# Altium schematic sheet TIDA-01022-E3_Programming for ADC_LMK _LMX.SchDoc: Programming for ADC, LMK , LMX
size 431 x 279 mm; Date: Not shown in title block; ApprovedBy: Not shown in title block; CheckedBy: Not shown in title block; Author: Not shown in title block; CompanyName: Not shown in title block; DrawnBy: Avinash N; Engineer: Anbu Mani; Organization: Not shown in title block; Address1: Not shown in title block; Address2: Not shown in title block; Address3: Not shown in title block; Address4: Not shown in title block; DocumentNumber: 1; Revision: Use project parameter SCH_Rev; SheetNumber: 15; SheetTotal: 26; PageSetup: Record=PageOptions¦CenterHorizontal=True¦CenterVertical=True¦PrintScale=1.00¦XCorrection=1.00¦YCorrection=1.00¦PrintKind=0¦BorderSize=5000000¦LeftOffset=0¦BottomOffset=0¦Orientation=2¦PaperLength=1000¦PaperWidth=1000¦Scale=100¦PaperSource=15¦PrintQuality=600¦MediaType=1¦DitherType=10¦PaperKind=Letter¦PrintScaleMode=1
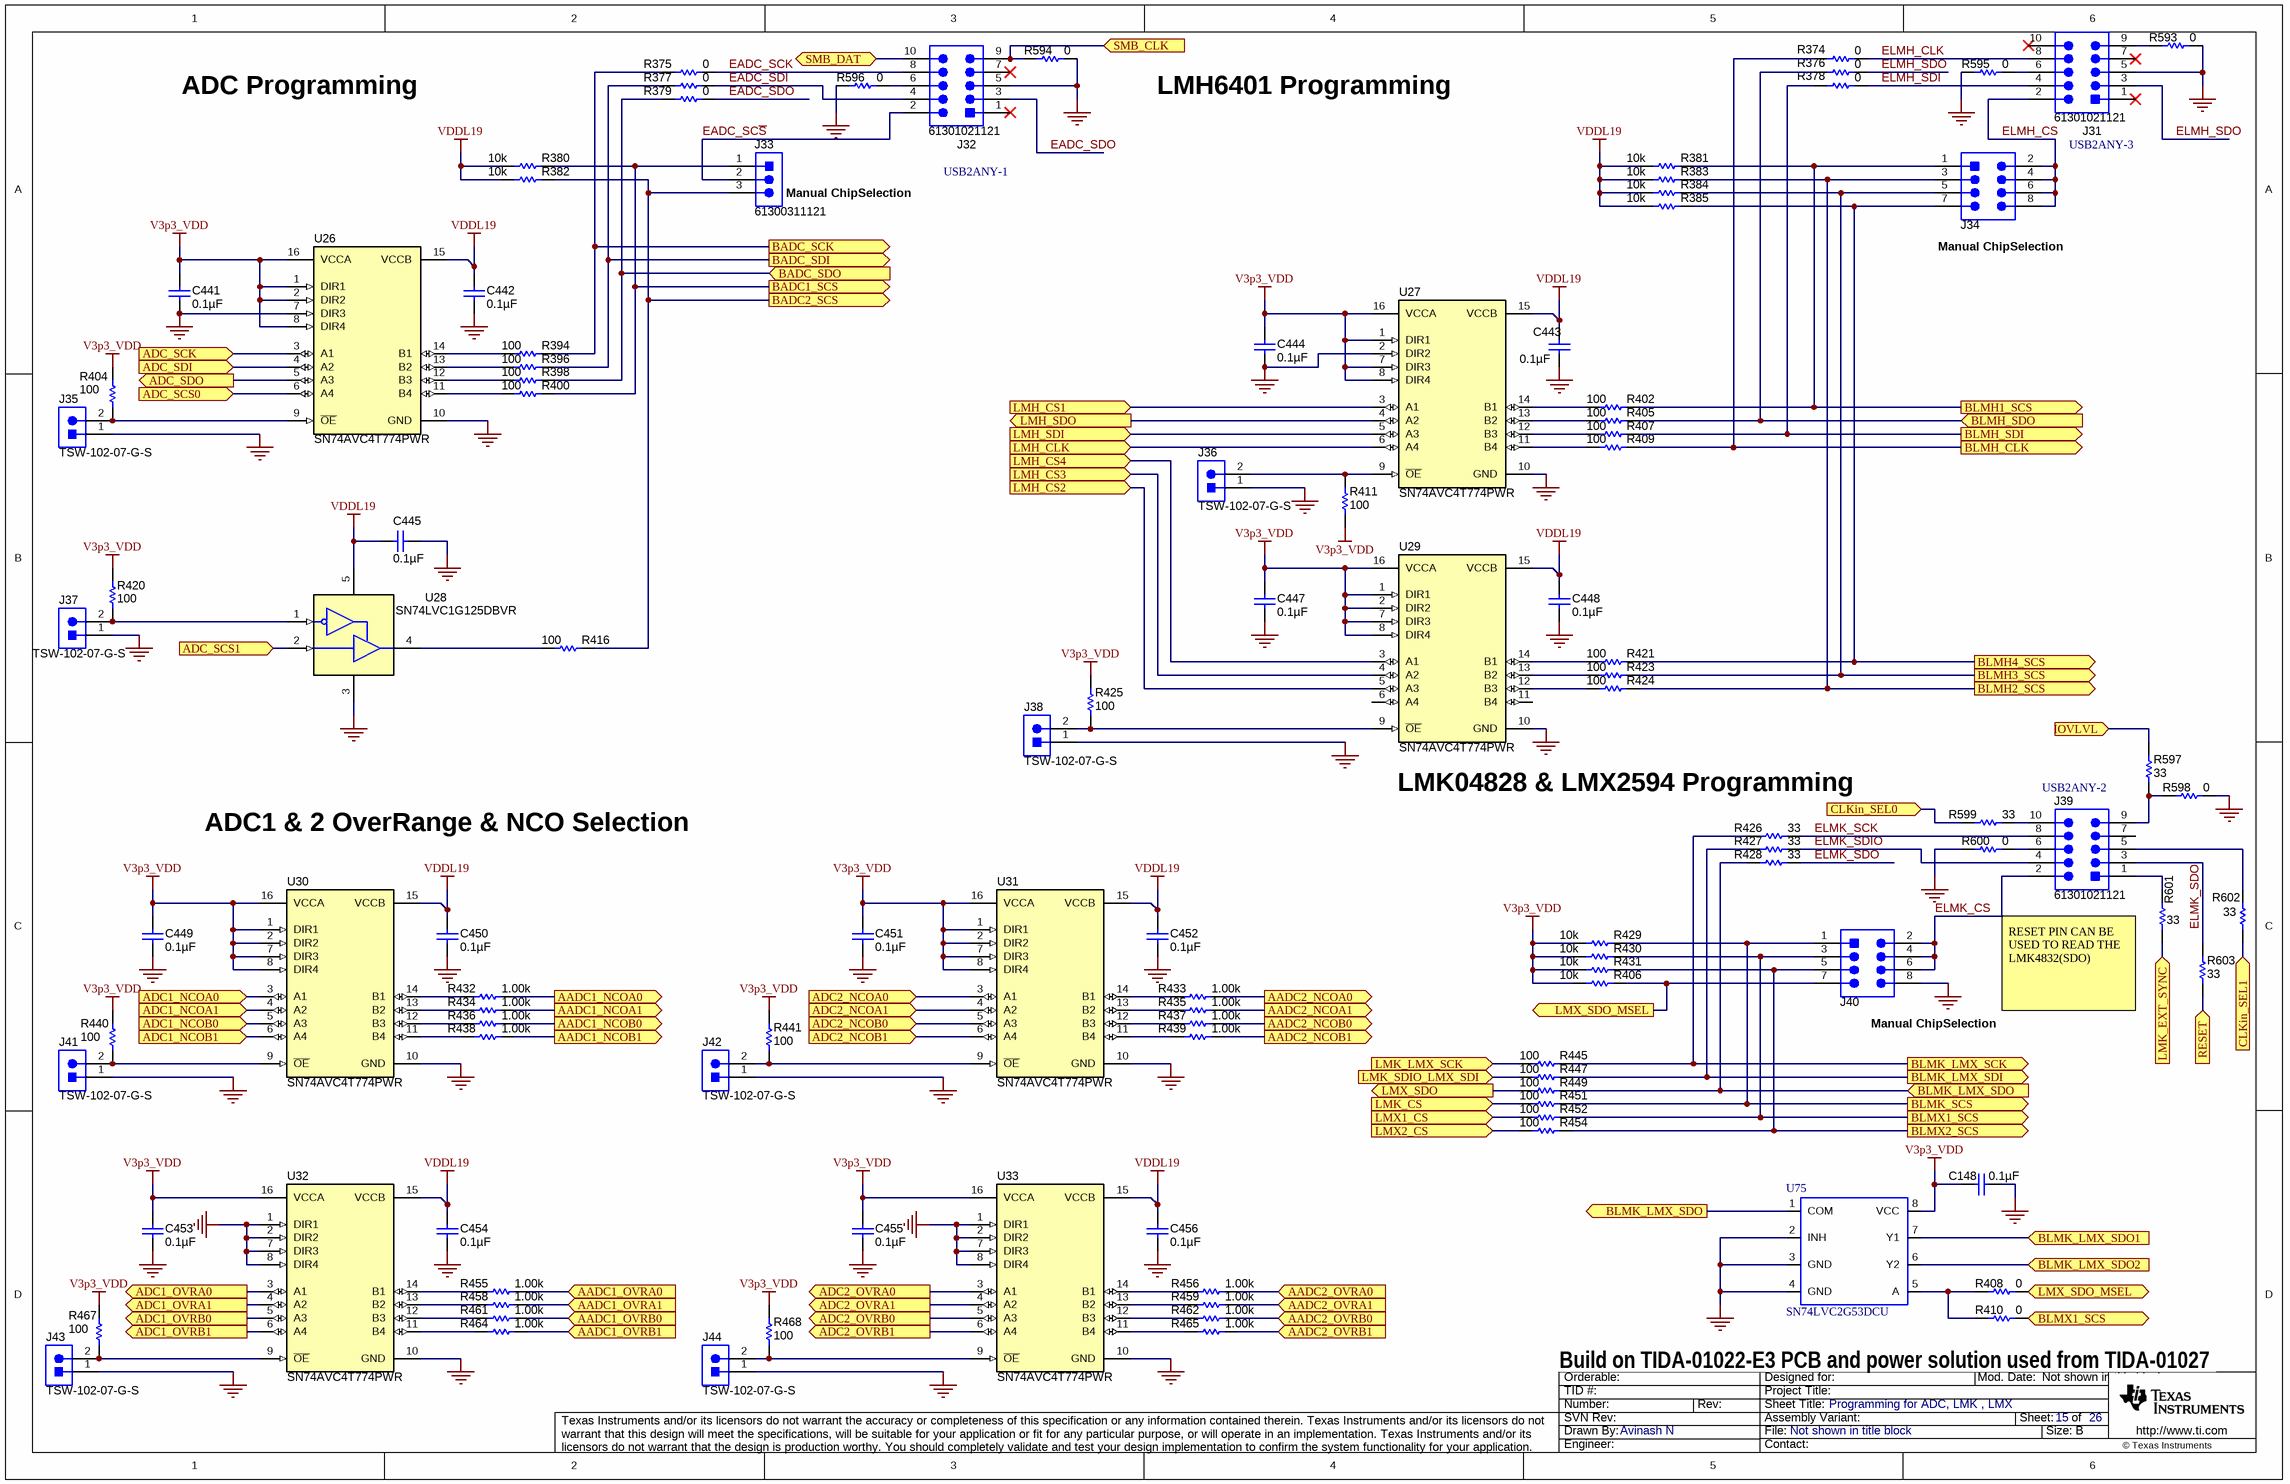
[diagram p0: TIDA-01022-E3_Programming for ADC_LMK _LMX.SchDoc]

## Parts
C148  ValueDisplayed: 0.1µF  [0603]  (hidden comment: C0603C104J3RACTU)
C441  ValueDisplayed: 0.1µF  [0603]  (hidden comment: C0603C104J3RACTU)
C442  ValueDisplayed: 0.1µF  [0603]  (hidden comment: C0603C104J3RACTU)
C443  ValueDisplayed: 0.1µF  [0603]  (hidden comment: C0603C104J3RACTU)
C444  ValueDisplayed: 0.1µF  [0603]  (hidden comment: C0603C104J3RACTU)
C445  ValueDisplayed: 0.1µF  [0603]  (hidden comment: C0603C104J3RACTU)
C447  ValueDisplayed: 0.1µF  [0603]  (hidden comment: C0603C104J3RACTU)
C448  ValueDisplayed: 0.1µF  [0603]  (hidden comment: C0603C104J3RACTU)
C449  ValueDisplayed: 0.1µF  [0603]  (hidden comment: C0603C104J3RACTU)
C450  ValueDisplayed: 0.1µF  [0603]  (hidden comment: C0603C104J3RACTU)
C451  ValueDisplayed: 0.1µF  [0603]  (hidden comment: C0603C104J3RACTU)
C452  ValueDisplayed: 0.1µF  [0603]  (hidden comment: C0603C104J3RACTU)
C453  ValueDisplayed: 0.1µF  [0603]  (hidden comment: C0603C104J3RACTU)
C454  ValueDisplayed: 0.1µF  [0603]  (hidden comment: C0603C104J3RACTU)
C455  ValueDisplayed: 0.1µF  [0603]  (hidden comment: C0603C104J3RACTU)
C456  ValueDisplayed: 0.1µF  [0603]  (hidden comment: C0603C104J3RACTU)
J31  61301021121  [WURTH_61301021121]
J32  61301021121  [WURTH_61301021121]
J33  61300311121  [WURTH_61300311121]
J34  TSW-104-07-G-D  [TSW-104-07-G-D]  (value not drawn)
J35  TSW-102-07-G-S  [TSW-102-07-G-S]
J36  TSW-102-07-G-S  [TSW-102-07-G-S]
J37  TSW-102-07-G-S  [TSW-102-07-G-S]
J38  TSW-102-07-G-S  [TSW-102-07-G-S]
J39  61301021121  [WURTH_61301021121]
J40  TSW-104-07-G-D  [TSW-104-07-G-D]  (value not drawn)
J41  TSW-102-07-G-S  [TSW-102-07-G-S]
J42  TSW-102-07-G-S  [TSW-102-07-G-S]
J43  TSW-102-07-G-S  [TSW-102-07-G-S]
J44  TSW-102-07-G-S  [TSW-102-07-G-S]
R374  ValueDisplayed: 0  [0603]  (hidden comment: CRCW06030000Z0EA)
R375  ValueDisplayed: 0  [0603]  (hidden comment: CRCW06030000Z0EA)
R376  ValueDisplayed: 0  [0603]  (hidden comment: CRCW06030000Z0EA)
R377  ValueDisplayed: 0  [0603]  (hidden comment: CRCW06030000Z0EA)
R378  ValueDisplayed: 0  [0603]  (hidden comment: CRCW06030000Z0EA)
R379  ValueDisplayed: 0  [0603]  (hidden comment: CRCW06030000Z0EA)
R380  ValueDisplayed: 10k  [0603]  (hidden comment: CRCW060310K0JNEA)
R381  ValueDisplayed: 10k  [0603]  (hidden comment: CRCW060310K0JNEA)
R382  ValueDisplayed: 10k  [0603]  (hidden comment: CRCW060310K0JNEA)
R383  ValueDisplayed: 10k  [0603]  (hidden comment: CRCW060310K0JNEA)
R384  ValueDisplayed: 10k  [0603]  (hidden comment: CRCW060310K0JNEA)
R385  ValueDisplayed: 10k  [0603]  (hidden comment: CRCW060310K0JNEA)
R394  ValueDisplayed: 100  [0603]  (hidden comment: RC0603FR-07100RL)
R396  ValueDisplayed: 100  [0603]  (hidden comment: RC0603FR-07100RL)
R398  ValueDisplayed: 100  [0603]  (hidden comment: RC0603FR-07100RL)
R400  ValueDisplayed: 100  [0603]  (hidden comment: RC0603FR-07100RL)
R402  ValueDisplayed: 100  [0603]  (hidden comment: RC0603FR-07100RL)
R404  ValueDisplayed: 100  [0603]  (hidden comment: RC0603FR-07100RL)
R405  ValueDisplayed: 100  [0603]  (hidden comment: RC0603FR-07100RL)
R406  ValueDisplayed: 10k  [0603]  (hidden comment: CRCW060310K0JNEA)
R407  ValueDisplayed: 100  [0603]  (hidden comment: RC0603FR-07100RL)
R408  ValueDisplayed: 0  [0603]  (hidden comment: CRCW06030000Z0EA)
R409  ValueDisplayed: 100  [0603]  (hidden comment: RC0603FR-07100RL)
R410  ValueDisplayed: 0  [0603]  (hidden comment: CRCW06030000Z0EA)
R411  ValueDisplayed: 100  [0603]  (hidden comment: RC0603FR-07100RL)
R416  ValueDisplayed: 100  [0603]  (hidden comment: RC0603FR-07100RL)
R420  ValueDisplayed: 100  [0603]  (hidden comment: RC0603FR-07100RL)
R421  ValueDisplayed: 100  [0603]  (hidden comment: RC0603FR-07100RL)
R423  ValueDisplayed: 100  [0603]  (hidden comment: RC0603FR-07100RL)
R424  ValueDisplayed: 100  [0603]  (hidden comment: RC0603FR-07100RL)
R425  ValueDisplayed: 100  [0603]  (hidden comment: RC0603FR-07100RL)
R426  ValueDisplayed: 33  [0603]  (hidden comment: CRCW060333R0JNEA)
R427  ValueDisplayed: 33  [0603]  (hidden comment: CRCW060333R0JNEA)
R428  ValueDisplayed: 33  [0603]  (hidden comment: CRCW060333R0JNEA)
R429  ValueDisplayed: 10k  [0603]  (hidden comment: CRCW060310K0JNEA)
R430  ValueDisplayed: 10k  [0603]  (hidden comment: CRCW060310K0JNEA)
R431  ValueDisplayed: 10k  [0603]  (hidden comment: CRCW060310K0JNEA)
R432  ValueDisplayed: 1.00k  [0603]  (hidden comment: CRCW06031K00FKEA)
R433  ValueDisplayed: 1.00k  [0603]  (hidden comment: CRCW06031K00FKEA)
R434  ValueDisplayed: 1.00k  [0603]  (hidden comment: CRCW06031K00FKEA)
R435  ValueDisplayed: 1.00k  [0603]  (hidden comment: CRCW06031K00FKEA)
R436  ValueDisplayed: 1.00k  [0603]  (hidden comment: CRCW06031K00FKEA)
R437  ValueDisplayed: 1.00k  [0603]  (hidden comment: CRCW06031K00FKEA)
R438  ValueDisplayed: 1.00k  [0603]  (hidden comment: CRCW06031K00FKEA)
R439  ValueDisplayed: 1.00k  [0603]  (hidden comment: CRCW06031K00FKEA)
R440  ValueDisplayed: 100  [0603]  (hidden comment: RC0603FR-07100RL)
R441  ValueDisplayed: 100  [0603]  (hidden comment: RC0603FR-07100RL)
R445  ValueDisplayed: 100  [0603]  (hidden comment: RC0603FR-07100RL)
R447  ValueDisplayed: 100  [0603]  (hidden comment: RC0603FR-07100RL)
R449  ValueDisplayed: 100  [0603]  (hidden comment: RC0603FR-07100RL)
R451  ValueDisplayed: 100  [0603]  (hidden comment: RC0603FR-07100RL)
R452  ValueDisplayed: 100  [0603]  (hidden comment: RC0603FR-07100RL)
R454  ValueDisplayed: 100  [0603]  (hidden comment: RC0603FR-07100RL)
R455  ValueDisplayed: 1.00k  [0603]  (hidden comment: CRCW06031K00FKEA)
R456  ValueDisplayed: 1.00k  [0603]  (hidden comment: CRCW06031K00FKEA)
R458  ValueDisplayed: 1.00k  [0603]  (hidden comment: CRCW06031K00FKEA)
R459  ValueDisplayed: 1.00k  [0603]  (hidden comment: CRCW06031K00FKEA)
R461  ValueDisplayed: 1.00k  [0603]  (hidden comment: CRCW06031K00FKEA)
R462  ValueDisplayed: 1.00k  [0603]  (hidden comment: CRCW06031K00FKEA)
R464  ValueDisplayed: 1.00k  [0603]  (hidden comment: CRCW06031K00FKEA)
R465  ValueDisplayed: 1.00k  [0603]  (hidden comment: CRCW06031K00FKEA)
R467  ValueDisplayed: 100  [0603]  (hidden comment: RC0603FR-07100RL)
R468  ValueDisplayed: 100  [0603]  (hidden comment: RC0603FR-07100RL)
R593  ValueDisplayed: 0  [0603]  (hidden comment: CRCW06030000Z0EA)
R594  ValueDisplayed: 0  [0603]  (hidden comment: CRCW06030000Z0EA)
R595  ValueDisplayed: 0  [0603]  (hidden comment: CRCW06030000Z0EA)
R596  ValueDisplayed: 0  [0603]  (hidden comment: CRCW06030000Z0EA)
R597  ValueDisplayed: 33  [0603]  (hidden comment: CRCW060333R0JNEA)
R598  ValueDisplayed: 0  [0603]  (hidden comment: CRCW06030000Z0EA)
R599  ValueDisplayed: 33  [0603]  (hidden comment: CRCW060333R0JNEA)
R600  ValueDisplayed: 0  [0603]  (hidden comment: CRCW06030000Z0EA)
R601  ValueDisplayed: 33  [0603]  (hidden comment: CRCW060333R0JNEA)
R602  ValueDisplayed: 33  [0603]  (hidden comment: CRCW060333R0JNEA)
R603  ValueDisplayed: 33  [0603]  (hidden comment: CRCW060333R0JNEA)
U26  SN74AVC4T774PWR  [PW0016A_N]
U27  SN74AVC4T774PWR  [PW0016A_N]
U28  SN74LVC1G125DBVR  [DBV0005A_N]
U29  SN74AVC4T774PWR  [PW0016A_N]
U30  SN74AVC4T774PWR  [PW0016A_N]
U31  SN74AVC4T774PWR  [PW0016A_N]
U32  SN74AVC4T774PWR  [PW0016A_N]
U33  SN74AVC4T774PWR  [PW0016A_N]
U75  SN74LVC2G53DCU  [DCU0008A_N]

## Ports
AADC1_NCOA0 (out), AADC1_NCOA1 (out), AADC1_NCOB0 (out), AADC1_NCOB1 (out), AADC1_OVRA0 (in), AADC1_OVRA1 (in), AADC1_OVRB0 (in), AADC1_OVRB1 (in), AADC2_NCOA0 (out), AADC2_NCOA1 (out), AADC2_NCOB0 (out), AADC2_NCOB1 (out), AADC2_OVRA0 (in), AADC2_OVRA1 (in), AADC2_OVRB0 (in), AADC2_OVRB1 (in), ADC1_NCOA0 (in), ADC1_NCOA1 (in), ADC1_NCOB0 (in), ADC1_NCOB1 (in), ADC1_OVRA0 (out), ADC1_OVRA1 (out), ADC1_OVRB0 (out), ADC1_OVRB1 (out), ADC2_NCOA0 (in), ADC2_NCOA1 (in), ADC2_NCOB0 (in), ADC2_NCOB1 (in), ADC2_OVRA0 (out), ADC2_OVRA1 (out), ADC2_OVRB0 (out), ADC2_OVRB1 (out), ADC_SCK (in), ADC_SCS0 (in), ADC_SCS1 (in), ADC_SDI (in), ADC_SDO (out), BADC1_SCS (out), BADC2_SCS (out), BADC_SCK (out), BADC_SDI (out), BADC_SDO (in), BLMH1_SCS (out), BLMH2_SCS (out), BLMH3_SCS (out), BLMH4_SCS (out), BLMH_CLK (out), BLMH_SDI (out), BLMH_SDO (in), BLMK_LMX_SCK (out), BLMK_LMX_SDI (out), BLMK_LMX_SDO1 (in), BLMK_LMX_SDO2 (in), BLMK_LMX_SDO (in), BLMK_LMX_SDO (out), BLMK_SCS (out), BLMX1_SCS (in), BLMX1_SCS (out), BLMX2_SCS (out), CLKin_SEL0 (in), CLKin_SEL1 (in), IOVLVL (in), LMH_CLK (in), LMH_CS1 (in), LMH_CS2 (in), LMH_CS3 (in), LMH_CS4 (in), LMH_SDI (in), LMH_SDO (out), LMK_CS (in), LMK_EXT_SYNC (in), LMK_LMX_SCK (in), LMK_SDIO_LMX_SDI (in), LMX1_CS (in), LMX2_CS (in), LMX_SDO (out), LMX_SDO_MSEL (in), LMX_SDO_MSEL (out), RESET (in), SMB_CLK (in), SMB_DAT (bidir)

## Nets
GND_PLL: C148.2 C441.1 C442.1 C443.1 C444.1 C445.1 C447.1 C448.1 C449.1 C450.1 C451.1 C452.1 C453.1 C454.1 C455.1 C456.1 J31.5 J32.5 J35.1 J36.1 J37.1 J38.1 J40.8 J41.1 J42.1 J43.1 J44.1 R593.2 R594.2 R595.1 R596.1 R598.2 R600.1 U26.7(DIR3) U26.10(GND) U27.2(DIR2) U27.10(GND) U28.3(GND) U29.10(GND) U30.10(GND) U31.10(GND) U32.1(DIR1) U32.2(DIR2) U32.7(DIR3) U32.8(DIR4) U32.10(GND) U33.1(DIR1) U33.2(DIR2) U33.7(DIR3) U33.8(DIR4) U33.10(GND) U75.2(INH) U75.3(GND) U75.4(GND)
V3p3_VDD: C148.1 C441.2 C444.2 C447.2 C449.2 C451.2 C453.2 C455.2 R404.1 R406.1 R411.1 R420.1 R425.1 R429.1 R430.1 R431.1 R440.1 R441.1 R467.1 R468.1 U26.1(DIR1) U26.2(DIR2) U26.8(DIR4) U26.16(VCCA) U27.1(DIR1) U27.7(DIR3) U27.8(DIR4) U27.16(VCCA) U29.1(DIR1) U29.2(DIR2) U29.7(DIR3) U29.8(DIR4) U29.16(VCCA) U30.1(DIR1) U30.2(DIR2) U30.7(DIR3) U30.8(DIR4) U30.16(VCCA) U31.1(DIR1) U31.2(DIR2) U31.7(DIR3) U31.8(DIR4) U31.16(VCCA) U32.16(VCCA) U33.16(VCCA) U75.8(VCC)
VDDL19: C442.2 C443.2 C445.2 C448.2 C450.2 C452.2 C454.2 C456.2 R380.1 R381.1 R382.1 R383.1 R384.1 R385.1 U26.15(VCCB) U27.15(VCCB) U28.5(VCC) U29.15(VCCB) U30.15(VCCB) U31.15(VCCB) U32.15(VCCB) U33.15(VCCB)
AADC1_NCOA0: R432.2 ; port AADC1_NCOA0
AADC1_NCOA1: R434.2 ; port AADC1_NCOA1
AADC1_NCOB0: R436.2 ; port AADC1_NCOB0
AADC1_NCOB1: R438.2 ; port AADC1_NCOB1
AADC1_OVRA0: R455.2 ; port AADC1_OVRA0
AADC1_OVRA1: R458.2 ; port AADC1_OVRA1
AADC1_OVRB0: R461.2 ; port AADC1_OVRB0
AADC1_OVRB1: R464.2 ; port AADC1_OVRB1
AADC2_NCOA0: R433.2 ; port AADC2_NCOA0
AADC2_NCOA1: R435.2 ; port AADC2_NCOA1
AADC2_NCOB0: R437.2 ; port AADC2_NCOB0
AADC2_NCOB1: R439.2 ; port AADC2_NCOB1
AADC2_OVRA0: R456.2 ; port AADC2_OVRA0
AADC2_OVRA1: R459.2 ; port AADC2_OVRA1
AADC2_OVRB0: R462.2 ; port AADC2_OVRB0
AADC2_OVRB1: R465.2 ; port AADC2_OVRB1
ADC1_NCOA0: U30.3(A1) ; port ADC1_NCOA0
ADC1_NCOA1: U30.4(A2) ; port ADC1_NCOA1
ADC1_NCOB0: U30.5(A3) ; port ADC1_NCOB0
ADC1_NCOB1: U30.6(A4) ; port ADC1_NCOB1
ADC1_OVRA0: U32.3(A1) ; port ADC1_OVRA0
ADC1_OVRA1: U32.4(A2) ; port ADC1_OVRA1
ADC1_OVRB0: U32.5(A3) ; port ADC1_OVRB0
ADC1_OVRB1: U32.6(A4) ; port ADC1_OVRB1
ADC2_NCOA0: U31.3(A1) ; port ADC2_NCOA0
ADC2_NCOA1: U31.4(A2) ; port ADC2_NCOA1
ADC2_NCOB0: U31.5(A3) ; port ADC2_NCOB0
ADC2_NCOB1: U31.6(A4) ; port ADC2_NCOB1
ADC2_OVRA0: U33.3(A1) ; port ADC2_OVRA0
ADC2_OVRA1: U33.4(A2) ; port ADC2_OVRA1
ADC2_OVRB0: U33.5(A3) ; port ADC2_OVRB0
ADC2_OVRB1: U33.6(A4) ; port ADC2_OVRB1
ADC_SCK: U26.3(A1) ; port ADC_SCK
ADC_SCS0: U26.6(A4) ; port ADC_SCS0
ADC_SCS1: U28.2(A) ; port ADC_SCS1
ADC_SDI: U26.4(A2) ; port ADC_SDI
ADC_SDO: U26.5(A3) ; port ADC_SDO
BADC1_SCS: J33.1 R380.2 R400.2 ; port BADC1_SCS
BADC2_SCS: J33.3 R382.2 R416.2 ; port BADC2_SCS
BADC_SCK: R375.1 R394.2 ; port BADC_SCK
BADC_SDI: R377.1 R396.2 ; port BADC_SDI
BADC_SDO: R379.1 R398.2 ; port BADC_SDO
BLMH1_SCS: J34.1 R381.2 R402.2 ; port BLMH1_SCS
BLMH2_SCS: J34.3 R383.2 R424.2 ; port BLMH2_SCS
BLMH3_SCS: J34.5 R384.2 R423.2 ; port BLMH3_SCS
BLMH4_SCS: J34.7 R385.2 R421.2 ; port BLMH4_SCS
BLMH_CLK: R374.1 R409.2 ; port BLMH_CLK
BLMH_SDI: R378.1 R407.2 ; port BLMH_SDI
BLMH_SDO: R376.1 R405.2 ; port BLMH_SDO
BLMK_LMX_SCK: R426.1 R445.2 ; port BLMK_LMX_SCK
BLMK_LMX_SDI: R427.1 R447.2 ; port BLMK_LMX_SDI
BLMK_LMX_SDO: R428.1 R449.2 U75.1(COM) ; port BLMK_LMX_SDO
BLMK_LMX_SDO1: U75.7(Y1) ; port BLMK_LMX_SDO1
BLMK_LMX_SDO2: U75.6(Y2) ; port BLMK_LMX_SDO2
BLMK_SCS: J40.1 R429.2 R451.2 ; port BLMK_SCS
BLMX1_SCS: J40.3 R410.2 R430.2 R452.2 ; port BLMX1_SCS
BLMX2_SCS: J40.5 R431.2 R454.2 ; port BLMX2_SCS
CLKin_SEL0: R599.2 ; port CLKin_SEL0
CLKin_SEL1: R602.1 ; port CLKin_SEL1
EADC_SCK: J32.8 R375.2
EADC_SC~{S}: J32.2 J33.2
EADC_SDI: J32.4 R377.2
EADC_SDO: J32.3 R379.2
ELMH_CLK: J31.8 R374.2
ELMH_CS: J31.2 J34.2 J34.4 J34.6 J34.8
ELMH_SDI: J31.4 R378.2
ELMH_SDO: J31.3 R376.2
ELMK_CS: J39.2 J40.2 J40.4 J40.6
ELMK_SCK: J39.8 R426.2
ELMK_SDIO: J39.4 R427.2
ELMK_SDO: J39.3 R428.2 R603.2
IOVLVL: R597.2 ; port IOVLVL
LMH_CLK: U27.6(A4) ; port LMH_CLK
LMH_CS1: U27.3(A1) ; port LMH_CS1
LMH_CS2: U29.5(A3) ; port LMH_CS2
LMH_CS3: U29.4(A2) ; port LMH_CS3
LMH_CS4: U29.3(A1) ; port LMH_CS4
LMH_SDI: U27.5(A3) ; port LMH_SDI
LMH_SDO: U27.4(A2) ; port LMH_SDO
LMK_CS: R451.1 ; port LMK_CS
LMK_EXT_SYNC: R601.1 ; port LMK_EXT_SYNC
LMK_LMX_SCK: R445.1 ; port LMK_LMX_SCK
LMK_SDIO_LMX_SDI: R447.1 ; port LMK_SDIO_LMX_SDI
LMX1_CS: R452.1 ; port LMX1_CS
LMX2_CS: R454.1 ; port LMX2_CS
LMX_SDO: R449.1 ; port LMX_SDO
LMX_SDO_MSEL: J40.7 R406.2 R408.2 ; port LMX_SDO_MSEL
RESET: R603.1 ; port RESET
SMB_CLK: J32.9 R594.1 ; port SMB_CLK
SMB_DAT: J32.10 ; port SMB_DAT
NetJ31_6: J31.6 R595.2
NetJ31_9: J31.9 R593.1
NetJ32_6: J32.6 R596.2
NetJ35_2: J35.2 R404.2 U26.9(~{OE})
NetJ36_2: J36.2 R411.2 U27.9(~{OE})
NetJ37_2: J37.2 R420.2 U28.1(~{OE})
NetJ38_2: J38.2 R425.2 U29.9(~{OE})
NetJ39_1: J39.1 R601.2
NetJ39_5: J39.5 R602.2
NetJ39_6: J39.6 R600.2
NetJ39_9: J39.9 R597.1 R598.1
NetJ39_10: J39.10 R599.1
NetJ41_2: J41.2 R440.2 U30.9(~{OE})
NetJ42_2: J42.2 R441.2 U31.9(~{OE})
NetJ43_2: J43.2 R467.2 U32.9(~{OE})
NetJ44_2: J44.2 R468.2 U33.9(~{OE})
NetR394_1: R394.1 U26.14(B1)
NetR396_1: R396.1 U26.13(B2)
NetR398_1: R398.1 U26.12(B3)
NetR400_1: R400.1 U26.11(B4)
NetR402_1: R402.1 U27.14(B1)
NetR405_1: R405.1 U27.13(B2)
NetR407_1: R407.1 U27.12(B3)
NetR408_1: R408.1 R410.1 U75.5(A)
NetR409_1: R409.1 U27.11(B4)
NetR416_1: R416.1 U28.4(Y)
NetR421_1: R421.1 U29.14(B1)
NetR423_1: R423.1 U29.13(B2)
NetR424_1: R424.1 U29.12(B3)
NetR432_1: R432.1 U30.14(B1)
NetR433_1: R433.1 U31.14(B1)
NetR434_1: R434.1 U30.13(B2)
NetR435_1: R435.1 U31.13(B2)
NetR436_1: R436.1 U30.12(B3)
NetR437_1: R437.1 U31.12(B3)
NetR438_1: R438.1 U30.11(B4)
NetR439_1: R439.1 U31.11(B4)
NetR455_1: R455.1 U32.14(B1)
NetR456_1: R456.1 U33.14(B1)
NetR458_1: R458.1 U32.13(B2)
NetR459_1: R459.1 U33.13(B2)
NetR461_1: R461.1 U32.12(B3)
NetR462_1: R462.1 U33.12(B3)
NetR464_1: R464.1 U32.11(B4)
NetR465_1: R465.1 U33.11(B4)

Not connected (* = marked no-connect by the designer): J31 1* 7* 10*; J32 1* 7*; J39 7; U29 6(A4) 11(B4)

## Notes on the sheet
- ADC Programming
- LMH6401 Programming
- USB2ANY-3
- (near J33) Manual ChipSelection
- USB2ANY-1
- (near J34) Manual ChipSelection
- ADC1 & 2 OverRange & NCO Selection
- LMK04828 & LMX2594 Programming
- (near J39) USB2ANY-2
- (near J40) Manual ChipSelection
- RESET PIN CAN BE USED TO READ THE LMK4832(SDO)
- (near R410) Build on TIDA-01022-E3 PCB and power solution used from TIDA-01027

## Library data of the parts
C148 C441-C445 C447-C456 = C0603C104J3RACTU: CAP, CERM, 0.1uF, 25V, +/-5%, X7R, 0603; Manufacturer: Kemet; Polarized: N; TaMax_C: 125; TaMin_C: -55; Tolerance_%: 5; VDC_V: 25; Cap_F: 0.0000001; CompType: Capacitor; Value1: Unknown; U/M: EA
J31 J32 J39 = 61301021121: Header, 2.54 mm, 5x2, Gold, TH; Manufacturer: Wurth Elektronik; SymbolCreator: a0412235; Green_Lifecycle: Active; Green_REACh: Passed
J33 = 61300311121: Header, 2.54 mm, 3x1, Gold, TH; Manufacturer: Wurth Elektronik; SymbolCreator: a0799628
J34 J40 = TSW-104-07-G-D: Header, 100mil, 4x2, Gold, TH; Manufacturer: Samtec; SymbolCreator: a0411947; Pitch_mm: 2.54; Gender: Male; Shrouded: N; Row_Count: 2; Current_A: 6.3; Voltage_V: 550; Cert_CSA: Y
J35-J38 J41-J44 = TSW-102-07-G-S: Header, 100mil, 2x1, Gold, TH; Manufacturer: Samtec; SymbolCreator: a0412235; Pitch_mm: 2.54; Gender: Male; Shrouded: N; Row_Count: 1; Current_A: 6.3; Voltage_V: 550; Cert_CSA: Y
R374-R379 R408 R410 R593-R596 R598 R600 = CRCW06030000Z0EA: RES, 0, 5%, 0.1 W, 0603; Manufacturer: Vishay-Dale; CompType: Resistor; Value: 0; Value_Code: 0000; Tolerance_%: 5; Power_W: 0.1; Value2: 0.1W; VDC_V: 75; TempCo: 200 ppm/C; SizeArea_mm2: 1.28; SizeX_mm: 1.6; SizeY_mm: 0.8; SizeZ_mm: 1; EIA_Code: E24; U/M: EA; AEC Category: Q200
R380-R385 R406 R429-R431 = CRCW060310K0JNEA: RES, 10 k, 5%, 0.1 W, 0603; Manufacturer: Vishay-Dale; CompType: Resistor; Value: 10k; Res_ohm: 10000; Value_Code: 10k0; Tolerance_%: 5; Power_W: 0.1; Value2: 0.1W; VDC_V: 75; TempCo: 200 ppm/C; SizeArea_mm2: 1.28; SizeX_mm: 1.6; SizeY_mm: 0.8; SizeZ_mm: 1; EIA_Code: E24; U/M: EA; AEC Category: Q200
R394 R396 R398 R400 R402 R404 R405 R407 R409 R411 R416 R420 R421 R423-R425 R440 R441 R445 R447 R449 R451 R452 R454 R467 R468 = RC0603FR-07100RL: RES, 100, 1%, 0.1 W, 0603; Manufacturer: Yageo America; CompType: Resistor; Value: 100; Value_Code: 100R; Tolerance_%: 1; Power_W: 0.1; Value2: 0.1W; VDC_V: 150; TempCo: 200 ppm/C; SizeArea_mm2: 1.28; SizeX_mm: 1.6; SizeY_mm: 0.8; EIA_Code: E96; U/M: EA; AEC Category: Q200
R426-R428 R597 R599 R601-R603 = CRCW060333R0JNEA: RES, 33, 5%, 0.1 W, 0603; Manufacturer: Vishay-Dale; CompType: Resistor; Value: 33; Value_Code: 33R0; Tolerance_%: 5; Power_W: 0.1; Value2: 0.1W; VDC_V: 75; TempCo: 200 ppm/C; SizeArea_mm2: 1.28; SizeX_mm: 1.6; SizeY_mm: 0.8; SizeZ_mm: 1; EIA_Code: E24; U/M: EA; AEC Category: Q200
R432-R439 R455 R456 R458 R459 R461 R462 R464 R465 = CRCW06031K00FKEA: RES, 1.00 k, 1%, 0.1 W, 0603; Manufacturer: Vishay-Dale; CompType: Resistor; Value: 1.00k; Res_ohm: 1000; Value_Code: 1k00; Tolerance_%: 1; Power_W: 0.1; Value2: 0.1W; VDC_V: 75; TempCo: 100 ppm/C; SizeArea_mm2: 1.28; SizeX_mm: 1.6; SizeY_mm: 0.8; EIA_Code: E96; U/M: EA; AEC Category: Q200
U26 U27 U29-U33 = SN74AVC4T774PWR: 4-Bit Dual-Supply Bus Transceiver With Configurable Voltage-Level Shifting and 3-State Outputs, PW0016A (TSSOP-16); Manufacturer: Texas Instruments; SymbolCreator: a0411947; SizeArea_mm2: 32; SizeAreaWB_mm2: 58.8; SizeX_mm: 6.4; SizeY_mm: 5; SizeZ_mm: 1.2; CompType: IC; U/M: EA
U28 = SN74LVC1G125DBVR: Single Bus Buffer Gate With 3-State Outputs, DBV0005A (SOT-5); Alternate PartNumber: SN74LVC1G125DBVT; Manufacturer: Texas Instruments; SymbolCreator: Altium; SizeArea_mm2: 8.12; SizeAreaWB_mm2: 14.82; SizeX_mm: 2.8; SizeY_mm: 2.9; SizeZ_mm: 1.45; CompType: IC; U/M: EA
U75 = SN74LVC2G53DCU: IC, SPDT Analog Switch; Manufacturer: TI; Alternate Manufacturer: None; Area: 36735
